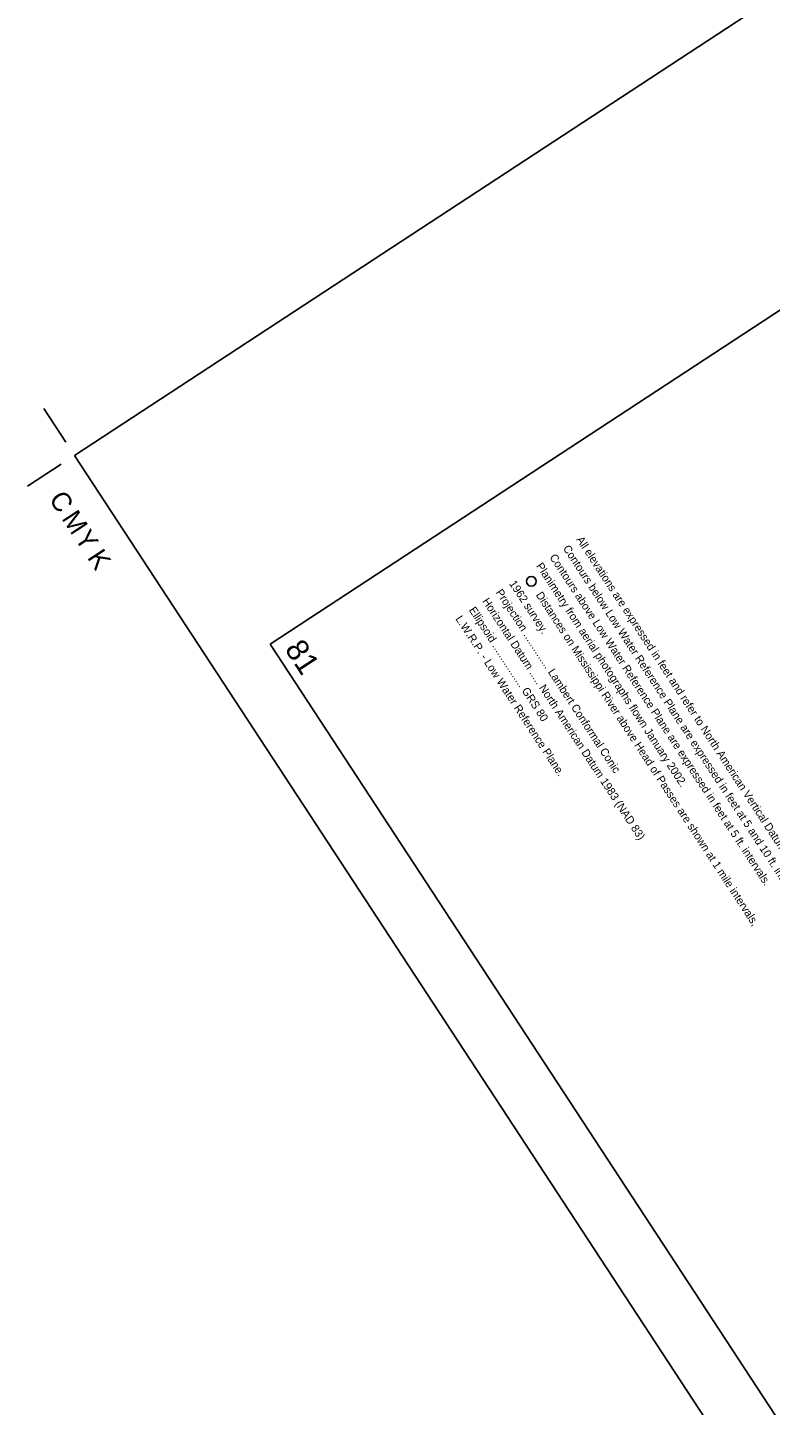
# Model space of a CAD drawing. Extents: x 3945642 to 3966284, y 206476 to 228921.
# Drawn here: x 3945642 to 3949497, y 217128 to 224274 of the extents above; entities that cross this region are included whole.
import ezdxf

# ---------------------------------------------------------------- set-up
doc = ezdxf.new("R2010")
doc.units = 0
for name, color, linetype in [('G-ANNO-NPLT', 7, 'Continuous'), ('V-ANNO-DIMS', 7, 'Continuous'), ('V-ANNO-NOTE', 7, 'Continuous'), ('V-ANNO-SYMB', 7, 'Continuous'), ('V-ANNO-TEXT', 7, 'Continuous')]:
    doc.layers.add(name, color=color, linetype=linetype)

msp = doc.modelspace()

# ---------------------------------------------------------------- linework, layer by layer
at = {"layer": 'G-ANNO-NPLT'}
msp.add_lwpolyline([(3945886.4, 222055.1), (3955932.9, 206719.5), (3966040.4, 213341.1), (3955993.9, 228676.6)], close=True, dxfattribs=at)
at = {"layer": 'V-ANNO-DIMS'}
for p, q in [((3945840.7, 222124.8), (3945726.6, 222299.1)), ((3945816.7, 222009.4), (3945642.4, 221895.3))]:
    msp.add_line(p, q, dxfattribs=at)
at = {"layer": 'V-ANNO-NOTE'}
msp.add_circle((3948256.3, 221402.3), 25, dxfattribs=at)
at = {"layer": 'V-ANNO-SYMB'}
msp.add_lwpolyline([(3946901.3, 221076.1), (3955966, 207239.3), (3965550.7, 213518.4), (3956486, 227355.2), (3946901.3, 221076.1)], dxfattribs=at)

# ---------------------------------------------------------------- texts
at = {"layer": 'V-ANNO-DIMS'}
for s, p in [('C', (3945750.6, 221829.3)), ('M', (3945816.8, 221728.2)), ('Y', (3945883, 221627.1)), ('K', (3945949.3, 221526.1))]:
    msp.add_text(s, height=99.6, rotation=303.22927, dxfattribs=at).set_placement(p)
at = {"layer": 'V-ANNO-NOTE'}
for s, rotation, p in [('All elevations are expressed in feet and refer to North American Vertical Datum of 1988.', 303.22928, (3948488.1, 221618.9)), ('Contours below Low Water Reference Plane are expressed in feet at 5 and 10 ft. intervals.', 303.22928, (3948418.4, 221573.2)), ('Planimetry from aerial photographs flown January 2002.', 303.22928, (3948279, 221481.9)), ('Contours above Low Water Reference Plane are expressed in feet at 5 ft. intervals.', 303.22928, (3948348.7, 221527.5)), ('1962 survey.', 303.22928, (3948139.5, 221390.5)), ('Projection .............. Lambert Conformal Conic', 303.22925, (3948069.8, 221344.8)), ('Distances on Mississippi River above Head of Passes are shown at 1 mile intervals,', 303.22928, (3948277.8, 221331.5)), ('Ellipsoid ................. GRS 80', 303.22925, (3947930.4, 221253.5)), ('Horizontal Datum ..... North American Datum 1983 (NAD 83)', 303.22925, (3948000.1, 221299.2)), ('L.W.R.P. - Low Water Reference Plane.', 303.22925, (3947860.7, 221207.8))]:
    msp.add_text(s, height=41.5, rotation=rotation, dxfattribs=at).set_placement(p)
at = {"layer": 'V-ANNO-TEXT'}
msp.add_text('81', height=115, rotation=303.22929, dxfattribs=at).set_placement((3946973.7, 221050.8))

doc.saveas('drawing.dxf')
